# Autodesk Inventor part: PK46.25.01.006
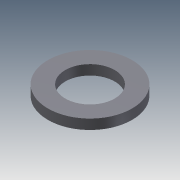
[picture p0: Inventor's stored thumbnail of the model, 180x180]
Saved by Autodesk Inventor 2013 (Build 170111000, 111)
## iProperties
Created: 2005-04
Part Number: PK46.25.01.006
Material: Steel, Mild
Document SubType Name: Modeling
Designer: salex
Manufacturer: Standard
Standards Organization: Custom
Density: 7.86 g/cm^3
Mass: 2333.48 g
Surface Area: 466.527 cm^2
Volume: 296.881 cm^3
Author: salex
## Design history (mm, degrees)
sketch "Эскиз1"
  geometry: C1 r 50 at (0, 0); C2 r 85 at (0, 0)
  constraints: 2 centre point, 1 coincident, 1 other
  dimensions: "d0" = 170 diameter of C2; "d1" = 100 diameter of C1
extrude "Выдавливание1" new body sketch "Эскиз1" distance "d2" = 20; taper "d3" = 0 deg
body "Solid1"
